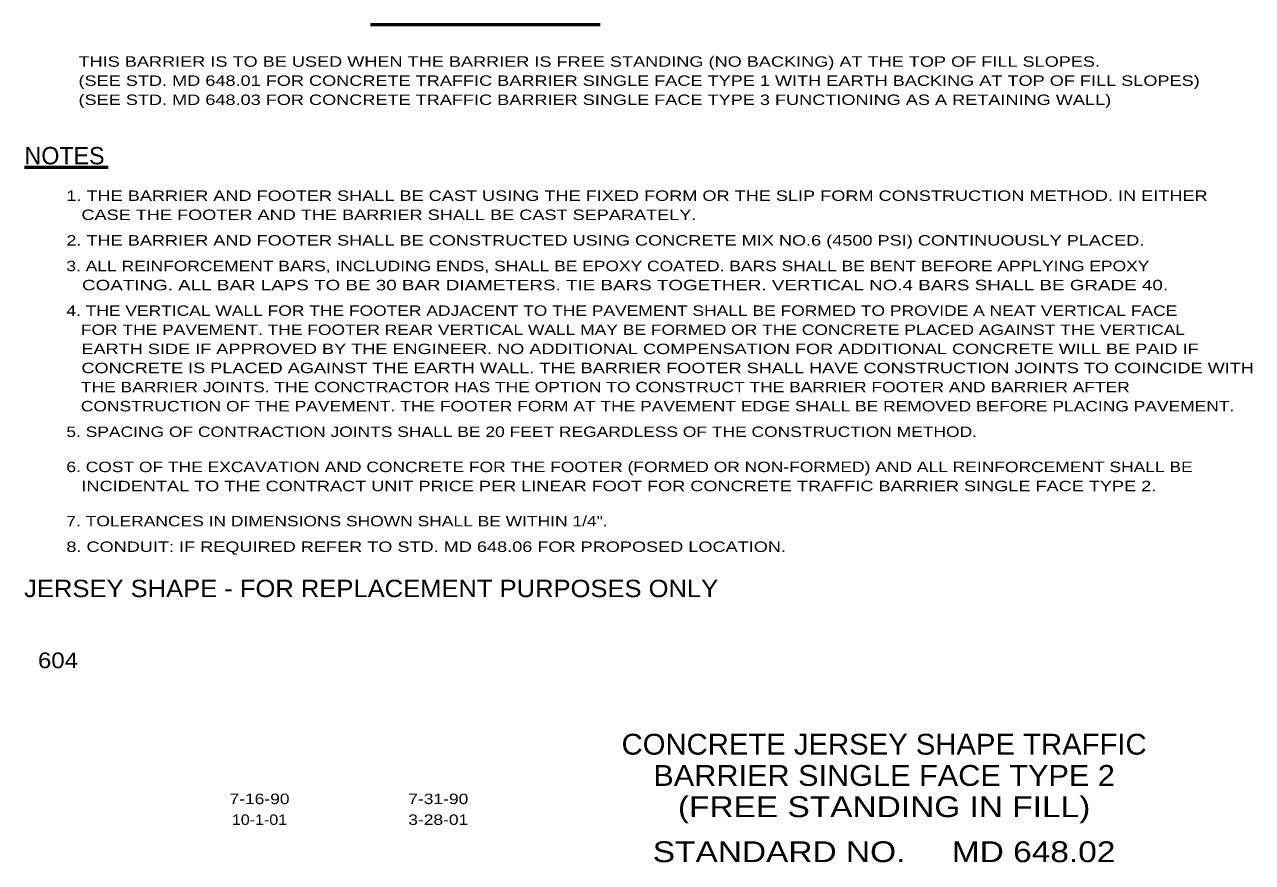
# Model space of a CAD drawing. Extents: x -16.43 to -9.36, y -8.57 to 1.26.
# Drawn here: x -16.43 to -9.36, y -8.57 to -3.75 of the extents above; entities that cross this region are included whole.
import ezdxf
from ezdxf.enums import TextEntityAlignment as Align

# ---------------------------------------------------------------- set-up
doc = ezdxf.new("R2010")
doc.units = 0
doc.header["$LTSCALE"] = 0.024
doc.layers.add('12', color=7, linetype='Continuous', lineweight=53)
doc.layers.add('13', color=7, linetype='Continuous', lineweight=53)

msp = doc.modelspace()

# ---------------------------------------------------------------- linework, layer by layer
at = {"layer": '12'}
msp.add_line((-14.44017, -3.74583), (-13.118, -3.74583), dxfattribs=at)
at = {"layer": '13'}
msp.add_line((-16.43333, -4.56783), (-15.952, -4.56783), dxfattribs=at)

# ---------------------------------------------------------------- texts
at = {"layer": '12'}
for s, height, width, p in [('THIS BARRIER IS TO BE USED WHEN THE BARRIER IS FREE STANDING (NO BACKING) AT THE TOP OF FILL SLOPES.', 0.06001, 1.3, (-16.12258, -3.98883)), ('(SEE STD. MD 648.01 FOR CONCRETE TRAFFIC BARRIER SINGLE FACE TYPE 1 WITH EARTH BACKING AT TOP OF FILL SLOPES)', 0.06001, 1.3, (-16.12258, -4.09883)), ('(SEE STD. MD 648.03 FOR CONCRETE TRAFFIC BARRIER SINGLE FACE TYPE 3 FUNCTIONING AS A RETAINING WALL)', 0.06001, 1.3, (-16.12258, -4.20892)), ('JERSEY SHAPE - FOR REPLACEMENT PURPOSES ONLY', 0.1, 1.1, (-16.4355, -7.04317))]:
    msp.add_text(s, height=height, dxfattribs=dict(at, width=width)).set_placement(p)
at = {"layer": '13'}
msp.add_text('NOTES', height=0.1, dxfattribs=at).set_placement((-16.43333, -4.55067))
for s, width, p in [('1. THE BARRIER AND FOOTER SHALL BE CAST USING THE FIXED FORM OR THE SLIP FORM CONSTRUCTION METHOD. IN EITHER', 1.3, (-16.19267, -4.76133)), ('   CASE THE FOOTER AND THE BARRIER SHALL BE CAST SEPARATELY.', 1.3, (-16.19267, -4.87133)), ('2. THE BARRIER AND FOOTER SHALL BE CONSTRUCTED USING CONCRETE MIX NO.6 (4500 PSI) CONTINUOUSLY PLACED.', 1.3, (-16.19267, -5.01867)), ('3. ALL REINFORCEMENT BARS, INCLUDING ENDS, SHALL BE EPOXY COATED. BARS SHALL BE BENT BEFORE APPLYING EPOXY', 1.25, (-16.19267, -5.16608)), ('   COATING. ALL BAR LAPS TO BE 30 BAR DIAMETERS. TIE BARS TOGETHER. VERTICAL NO.4 BARS SHALL BE GRADE 40.', 1.35, (-16.19267, -5.27608)), ('4. THE VERTICAL WALL FOR THE FOOTER ADJACENT TO THE PAVEMENT SHALL BE FORMED TO PROVIDE A NEAT VERTICAL FACE', 1.25, (-16.19267, -5.42342)), ('   FOR THE PAVEMENT. THE FOOTER REAR VERTICAL WALL MAY BE FORMED OR THE CONCRETE PLACED AGAINST THE VERTICAL', 1.25, (-16.19267, -5.53342)), ('   EARTH SIDE IF APPROVED BY THE ENGINEER. NO ADDITIONAL COMPENSATION FOR ADDITIONAL CONCRETE WILL BE PAID IF', 1.3, (-16.19267, -5.64342)), ('   CONCRETE IS PLACED AGAINST THE EARTH WALL. THE BARRIER FOOTER SHALL HAVE CONSTRUCTION JOINTS TO COINCIDE WITH', 1.3, (-16.19267, -5.7535)), ('   THE BARRIER JOINTS. THE CONCTRACTOR HAS THE OPTION TO CONSTRUCT THE BARRIER FOOTER AND BARRIER AFTER', 1.25, (-16.19267, -5.8635)), ('   CONSTRUCTION OF THE PAVEMENT. THE FOOTER FORM AT THE PAVEMENT EDGE SHALL BE REMOVED BEFORE PLACING PAVEMENT.', 1.25, (-16.19267, -5.9735)), ('5. SPACING OF CONTRACTION JOINTS SHALL BE 20 FEET REGARDLESS OF THE CONSTRUCTION METHOD.', 1.25, (-16.19267, -6.12083)), ('6. COST OF THE EXCAVATION AND CONCRETE FOR THE FOOTER (FORMED OR NON-FORMED) AND ALL REINFORCEMENT SHALL BE', 1.25, (-16.19267, -6.32317)), ('   INCIDENTAL TO THE CONTRACT UNIT PRICE PER LINEAR FOOT FOR CONCRETE TRAFFIC BARRIER SINGLE FACE TYPE 2.', 1.3, (-16.19267, -6.43317)), ('7. TOLERANCES IN DIMENSIONS SHOWN SHALL BE WITHIN 1/4".', 1.25, (-16.19267, -6.6355)), ('8. CONDUIT: IF REQUIRED REFER TO STD. MD 648.06 FOR PROPOSED LOCATION.', 1.3, (-16.19267, -6.78283))]:
    msp.add_text(s, height=0.06001, dxfattribs=dict(at, width=width)).set_placement(p)
for s, height, width, p in [('604', 0.09001, 1.15, (-16.24071, -7.45225)), ('CONCRETE JERSEY SHAPE TRAFFIC', 0.12, 1.05, (-11.48296, -7.95025)), ('BARRIER SINGLE FACE TYPE 2', 0.12, 1.1, (-11.48287, -8.13025)), ('7-16-90', 0.06, 1.25, (-15.08017, -8.235)), ('7-31-90', 0.06, 1.25, (-14.05067, -8.235)), ('(FREE STANDING IN FILL)', 0.12, 1.2, (-11.48292, -8.31025)), ('10-1-01', 0.06, 1.15, (-15.08017, -8.355)), ('3-28-01', 0.06, 1.25, (-14.05071, -8.355)), ('STANDARD NO.     MD 648.02', 0.12, 1.2, (-11.483, -8.56942))]:
    msp.add_text(s, height=height, dxfattribs=dict(at, width=width)).set_placement(p, align=Align.CENTER)

doc.saveas('drawing.dxf')
